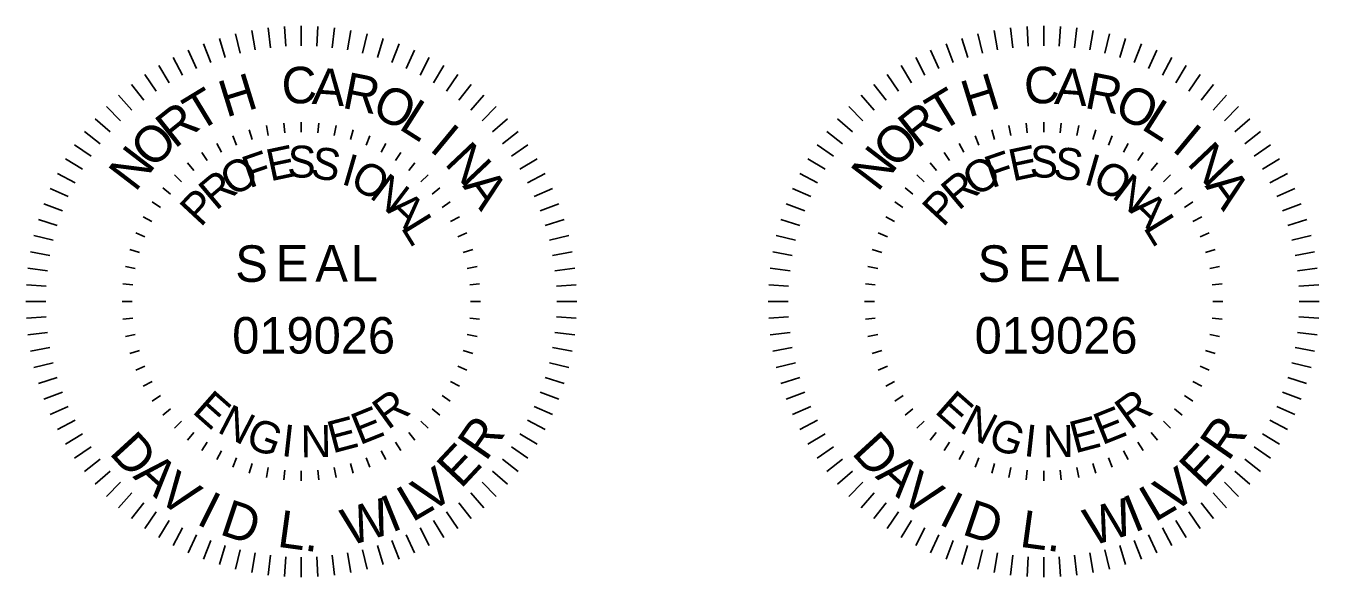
# Model space of a CAD drawing. Extents: x 1882804 to 1884487, y 844572 to 845443.
# Drawn here: x 1884080.2 to 1884256.3, y 845235.3 to 845310.3 of the extents above; entities that cross this region are included whole.
import ezdxf

# ---------------------------------------------------------------- set-up
doc = ezdxf.new("R2010")
doc.units = 0
doc.layers.add('Sheet Title CELL', color=7, linetype='Continuous')

msp = doc.modelspace()

# ---------------------------------------------------------------- linework, layer by layer
at = {"layer": 'Sheet Title CELL'}
for p, q in [((1884109.41, 845306.6), (1884108.76, 845309.24)), ((1884111.47, 845307.05), (1884110.98, 845309.71)), ((1884113.54, 845307.36), (1884113.22, 845310.05)), ((1884115.64, 845307.55), (1884115.47, 845310.26)), ((1884117.74, 845307.62), (1884117.74, 845310.33)), ((1884119.84, 845307.55), (1884120, 845310.26)), ((1884121.93, 845307.36), (1884122.26, 845310.05)), ((1884124.01, 845307.05), (1884124.5, 845309.71)), ((1884126.06, 845306.6), (1884126.71, 845309.24)), ((1884210.49, 845306.6), (1884209.84, 845309.24)), ((1884212.54, 845307.05), (1884212.05, 845309.71)), ((1884214.62, 845307.36), (1884214.29, 845310.05)), ((1884216.71, 845307.55), (1884216.55, 845310.26)), ((1884218.81, 845307.62), (1884218.81, 845310.33)), ((1884220.92, 845307.55), (1884221.08, 845310.26)), ((1884223.01, 845307.36), (1884223.34, 845310.05)), ((1884225.08, 845307.05), (1884225.57, 845309.71)), ((1884227.14, 845306.6), (1884227.79, 845309.24)), ((1884103.46, 845304.55), (1884102.35, 845307.02)), ((1884105.4, 845305.35), (1884104.44, 845307.89)), ((1884107.39, 845306.04), (1884106.58, 845308.63)), ((1884128.09, 845306.04), (1884128.89, 845308.63)), ((1884130.07, 845305.35), (1884131.04, 845307.89)), ((1884132.02, 845304.55), (1884133.13, 845307.02)), ((1884204.53, 845304.55), (1884203.42, 845307.02)), ((1884206.48, 845305.35), (1884205.52, 845307.89)), ((1884208.47, 845306.04), (1884207.66, 845308.63)), ((1884229.16, 845306.04), (1884229.97, 845308.63)), ((1884231.15, 845305.35), (1884232.11, 845307.89)), ((1884233.09, 845304.55), (1884234.2, 845307.02)), ((1884101.57, 845303.63), (1884100.31, 845306.03)), ((1884133.9, 845303.63), (1884135.16, 845306.03)), ((1884202.65, 845303.63), (1884201.39, 845306.03)), ((1884234.98, 845303.63), (1884236.24, 845306.03)), ((1884097.98, 845301.46), (1884096.43, 845303.69)), ((1884099.74, 845302.6), (1884098.34, 845304.92)), ((1884135.73, 845302.6), (1884137.14, 845304.92)), ((1884137.5, 845301.46), (1884139.04, 845303.69)), ((1884199.05, 845301.46), (1884197.51, 845303.69)), ((1884200.82, 845302.6), (1884199.41, 845304.92)), ((1884236.81, 845302.6), (1884238.21, 845304.92)), ((1884238.58, 845301.46), (1884240.12, 845303.69)), ((1884096.28, 845300.21), (1884094.61, 845302.34)), ((1884139.19, 845300.21), (1884140.86, 845302.34)), ((1884197.36, 845300.21), (1884195.69, 845302.34)), ((1884240.27, 845300.21), (1884241.94, 845302.34)), ((1884094.67, 845298.87), (1884092.87, 845300.9)), ((1884140.81, 845298.87), (1884142.61, 845300.9)), ((1884195.74, 845298.87), (1884193.95, 845300.9)), ((1884241.88, 845298.87), (1884243.68, 845300.9)), ((1884093.14, 845297.43), (1884091.22, 845299.34)), ((1884142.34, 845297.43), (1884144.25, 845299.34)), ((1884194.21, 845297.43), (1884192.3, 845299.34)), ((1884243.41, 845297.43), (1884245.33, 845299.34)), ((1884091.7, 845295.89), (1884089.67, 845297.69)), ((1884113.24, 845295.43), (1884112.98, 845296.76)), ((1884115.48, 845295.76), (1884115.35, 845297.11)), ((1884117.74, 845295.87), (1884117.74, 845297.22)), ((1884120, 845295.76), (1884120.13, 845297.11)), ((1884122.23, 845295.43), (1884122.5, 845296.76)), ((1884143.78, 845295.89), (1884145.81, 845297.69)), ((1884192.77, 845295.89), (1884190.75, 845297.69)), ((1884214.32, 845295.43), (1884214.05, 845296.76)), ((1884216.55, 845295.76), (1884216.42, 845297.11)), ((1884218.81, 845295.87), (1884218.81, 845297.22)), ((1884221.07, 845295.76), (1884221.2, 845297.11)), ((1884223.31, 845295.43), (1884223.58, 845296.76)), ((1884244.85, 845295.89), (1884246.88, 845297.69)), ((1884090.35, 845294.28), (1884088.22, 845295.95)), ((1884108.92, 845294.11), (1884108.4, 845295.37)), ((1884111.05, 845294.88), (1884110.65, 845296.17)), ((1884124.43, 845294.88), (1884124.82, 845296.17)), ((1884126.56, 845294.11), (1884127.07, 845295.37)), ((1884145.12, 845294.28), (1884147.26, 845295.95)), ((1884191.43, 845294.28), (1884189.29, 845295.95)), ((1884210, 845294.11), (1884209.48, 845295.37)), ((1884212.13, 845294.88), (1884211.73, 845296.17)), ((1884225.5, 845294.88), (1884225.9, 845296.17)), ((1884227.63, 845294.11), (1884228.15, 845295.37)), ((1884246.2, 845294.28), (1884248.34, 845295.95)), ((1884089.11, 845292.59), (1884086.88, 845294.13)), ((1884104.94, 845291.99), (1884104.18, 845293.11)), ((1884106.88, 845293.15), (1884106.24, 845294.34)), ((1884128.6, 845293.15), (1884129.24, 845294.34)), ((1884130.54, 845291.99), (1884131.29, 845293.11)), ((1884146.37, 845292.59), (1884148.6, 845294.13)), ((1884190.18, 845292.59), (1884187.95, 845294.13)), ((1884206.01, 845291.99), (1884205.26, 845293.11)), ((1884207.95, 845293.15), (1884207.31, 845294.34)), ((1884229.68, 845293.15), (1884230.31, 845294.34)), ((1884231.62, 845291.99), (1884232.37, 845293.11)), ((1884247.45, 845292.59), (1884249.68, 845294.13)), ((1884087.97, 845290.82), (1884085.64, 845292.23)), ((1884103.12, 845290.64), (1884102.26, 845291.68)), ((1884132.36, 845290.64), (1884133.21, 845291.68)), ((1884147.51, 845290.82), (1884149.83, 845292.23)), ((1884189.04, 845290.82), (1884186.72, 845292.23)), ((1884204.2, 845290.64), (1884203.34, 845291.68)), ((1884233.43, 845290.64), (1884234.29, 845291.68)), ((1884248.59, 845290.82), (1884250.91, 845292.23)), ((1884086.93, 845288.99), (1884084.53, 845290.25)), ((1884101.44, 845289.12), (1884100.49, 845290.08)), ((1884134.03, 845289.12), (1884134.99, 845290.08)), ((1884148.54, 845288.99), (1884150.94, 845290.25)), ((1884188.01, 845288.99), (1884185.61, 845290.25)), ((1884202.52, 845289.12), (1884201.56, 845290.08)), ((1884235.11, 845289.12), (1884236.07, 845290.08)), ((1884249.62, 845288.99), (1884252.02, 845290.25)), ((1884086.01, 845287.1), (1884083.54, 845288.22)), ((1884099.93, 845287.44), (1884098.88, 845288.3)), ((1884135.55, 845287.44), (1884136.6, 845288.3)), ((1884149.46, 845287.1), (1884151.93, 845288.22)), ((1884187.09, 845287.1), (1884184.62, 845288.22)), ((1884201, 845287.44), (1884199.95, 845288.3)), ((1884236.63, 845287.44), (1884237.67, 845288.3)), ((1884250.54, 845287.1), (1884253.01, 845288.22)), ((1884085.21, 845285.16), (1884082.67, 845286.12)), ((1884098.58, 845285.63), (1884097.45, 845286.38)), ((1884136.9, 845285.63), (1884138.02, 845286.38)), ((1884150.27, 845285.16), (1884152.8, 845286.12)), ((1884186.29, 845285.16), (1884183.75, 845286.12)), ((1884199.65, 845285.63), (1884198.53, 845286.38)), ((1884237.97, 845285.63), (1884239.1, 845286.38)), ((1884251.34, 845285.16), (1884253.88, 845286.12)), ((1884097.41, 845283.69), (1884096.22, 845284.33)), ((1884138.06, 845283.69), (1884139.26, 845284.33)), ((1884198.49, 845283.69), (1884197.3, 845284.33)), ((1884239.14, 845283.69), (1884240.33, 845284.33)), ((1884084.52, 845283.18), (1884081.94, 845283.98)), ((1884150.95, 845283.18), (1884153.54, 845283.98)), ((1884185.6, 845283.18), (1884183.01, 845283.98)), ((1884252.03, 845283.18), (1884254.62, 845283.98)), ((1884083.96, 845281.15), (1884081.33, 845281.8)), ((1884096.45, 845281.64), (1884095.2, 845282.16)), ((1884139.03, 845281.64), (1884140.28, 845282.16)), ((1884151.52, 845281.15), (1884154.15, 845281.8)), ((1884185.04, 845281.15), (1884182.4, 845281.8)), ((1884197.53, 845281.64), (1884196.27, 845282.16)), ((1884240.1, 845281.64), (1884241.36, 845282.16)), ((1884252.59, 845281.15), (1884255.23, 845281.8)), ((1884083.52, 845279.1), (1884080.85, 845279.58)), ((1884095.69, 845279.51), (1884094.39, 845279.91)), ((1884139.79, 845279.51), (1884141.09, 845279.91)), ((1884151.96, 845279.1), (1884154.62, 845279.58)), ((1884184.59, 845279.1), (1884181.93, 845279.58)), ((1884196.76, 845279.51), (1884195.47, 845279.91)), ((1884240.86, 845279.51), (1884242.16, 845279.91)), ((1884253.03, 845279.1), (1884255.7, 845279.58)), ((1884083.2, 845277.02), (1884080.51, 845277.35)), ((1884095.14, 845277.32), (1884093.81, 845277.58)), ((1884140.34, 845277.32), (1884141.67, 845277.58)), ((1884152.27, 845277.02), (1884154.96, 845277.35)), ((1884184.28, 845277.02), (1884181.59, 845277.35)), ((1884196.21, 845277.32), (1884194.89, 845277.58)), ((1884241.41, 845277.32), (1884242.74, 845277.58)), ((1884253.35, 845277.02), (1884256.04, 845277.35)), ((1884083.01, 845274.92), (1884080.31, 845275.09)), ((1884094.81, 845275.08), (1884093.46, 845275.22)), ((1884140.67, 845275.08), (1884142.02, 845275.22)), ((1884152.46, 845274.92), (1884155.17, 845275.09)), ((1884184.09, 845274.92), (1884181.38, 845275.09)), ((1884195.88, 845275.08), (1884194.53, 845275.22)), ((1884241.75, 845275.08), (1884243.09, 845275.22)), ((1884253.54, 845274.92), (1884256.25, 845275.09)), ((1884082.95, 845272.83), (1884080.24, 845272.83)), ((1884094.69, 845272.83), (1884093.34, 845272.83)), ((1884140.78, 845272.83), (1884142.13, 845272.83)), ((1884152.53, 845272.83), (1884155.24, 845272.83)), ((1884184.02, 845272.83), (1884181.31, 845272.83)), ((1884195.77, 845272.83), (1884194.42, 845272.83)), ((1884241.86, 845272.83), (1884243.21, 845272.83)), ((1884253.6, 845272.83), (1884256.31, 845272.83)), ((1884083.01, 845270.72), (1884080.31, 845270.56)), ((1884094.81, 845270.57), (1884093.46, 845270.44)), ((1884140.67, 845270.57), (1884142.02, 845270.44)), ((1884152.46, 845270.72), (1884155.17, 845270.56)), ((1884184.09, 845270.72), (1884181.38, 845270.56)), ((1884195.88, 845270.57), (1884194.53, 845270.44)), ((1884241.75, 845270.57), (1884243.09, 845270.44)), ((1884253.54, 845270.72), (1884256.25, 845270.56)), ((1884083.2, 845268.63), (1884080.51, 845268.31)), ((1884095.14, 845268.33), (1884093.81, 845268.07)), ((1884140.34, 845268.33), (1884141.67, 845268.07)), ((1884152.27, 845268.63), (1884154.96, 845268.31)), ((1884184.28, 845268.63), (1884181.59, 845268.31)), ((1884196.21, 845268.33), (1884194.88, 845268.07)), ((1884241.41, 845268.33), (1884242.74, 845268.07)), ((1884253.35, 845268.63), (1884256.04, 845268.31)), ((1884083.52, 845266.55), (1884080.85, 845266.07)), ((1884151.96, 845266.55), (1884154.62, 845266.07)), ((1884184.59, 845266.55), (1884181.93, 845266.07)), ((1884253.03, 845266.55), (1884255.7, 845266.07)), ((1884095.69, 845266.14), (1884094.39, 845265.74)), ((1884139.79, 845266.14), (1884141.09, 845265.74)), ((1884196.77, 845266.14), (1884195.47, 845265.74)), ((1884240.86, 845266.14), (1884242.16, 845265.74)), ((1884083.96, 845264.5), (1884081.33, 845263.85)), ((1884096.45, 845264.01), (1884095.2, 845263.49)), ((1884139.03, 845264.01), (1884140.28, 845263.49)), ((1884151.52, 845264.5), (1884154.15, 845263.85)), ((1884185.04, 845264.5), (1884182.4, 845263.85)), ((1884197.53, 845264.01), (1884196.27, 845263.49)), ((1884240.1, 845264.01), (1884241.36, 845263.49)), ((1884252.59, 845264.5), (1884255.23, 845263.85)), ((1884084.52, 845262.48), (1884081.94, 845261.67)), ((1884097.42, 845261.96), (1884096.22, 845261.32)), ((1884138.06, 845261.96), (1884139.26, 845261.32)), ((1884150.95, 845262.47), (1884153.54, 845261.67)), ((1884185.6, 845262.48), (1884183.01, 845261.67)), ((1884198.49, 845261.96), (1884197.3, 845261.32)), ((1884239.14, 845261.96), (1884240.33, 845261.32)), ((1884252.03, 845262.47), (1884254.61, 845261.67)), ((1884085.21, 845260.49), (1884082.67, 845259.53)), ((1884098.58, 845260.02), (1884097.45, 845259.27)), ((1884136.9, 845260.02), (1884138.02, 845259.27)), ((1884150.27, 845260.49), (1884152.8, 845259.53)), ((1884186.29, 845260.49), (1884183.75, 845259.53)), ((1884199.66, 845260.02), (1884198.53, 845259.27)), ((1884237.97, 845260.02), (1884239.1, 845259.27)), ((1884251.34, 845260.49), (1884253.88, 845259.53)), ((1884086.01, 845258.55), (1884083.54, 845257.43)), ((1884099.93, 845258.21), (1884098.88, 845257.35)), ((1884135.55, 845258.21), (1884136.6, 845257.35)), ((1884149.46, 845258.55), (1884151.93, 845257.43)), ((1884187.09, 845258.55), (1884184.62, 845257.43)), ((1884201, 845258.21), (1884199.95, 845257.35)), ((1884236.63, 845258.21), (1884237.67, 845257.35)), ((1884250.54, 845258.55), (1884253.01, 845257.43)), ((1884086.93, 845256.66), (1884084.53, 845255.4)), ((1884101.44, 845256.53), (1884100.49, 845255.57)), ((1884134.03, 845256.53), (1884134.99, 845255.57)), ((1884148.54, 845256.66), (1884150.94, 845255.4)), ((1884188.01, 845256.66), (1884185.61, 845255.4)), ((1884202.52, 845256.53), (1884201.56, 845255.57)), ((1884235.11, 845256.53), (1884236.07, 845255.57)), ((1884249.62, 845256.66), (1884252.02, 845255.4)), ((1884087.97, 845254.83), (1884085.64, 845253.42)), ((1884103.12, 845255.01), (1884102.26, 845253.97)), ((1884132.36, 845255.01), (1884133.21, 845253.97)), ((1884147.51, 845254.83), (1884149.83, 845253.42)), ((1884189.04, 845254.83), (1884186.72, 845253.42)), ((1884204.19, 845255.01), (1884203.34, 845253.97)), ((1884233.43, 845255.01), (1884234.29, 845253.97)), ((1884248.59, 845254.83), (1884250.91, 845253.42)), ((1884089.11, 845253.06), (1884086.88, 845251.52)), ((1884104.94, 845253.67), (1884104.18, 845252.54)), ((1884106.88, 845252.5), (1884106.24, 845251.31)), ((1884128.6, 845252.5), (1884129.24, 845251.31)), ((1884130.54, 845253.67), (1884131.29, 845252.54)), ((1884146.37, 845253.06), (1884148.6, 845251.52)), ((1884190.18, 845253.06), (1884187.95, 845251.52)), ((1884206.01, 845253.67), (1884205.26, 845252.54)), ((1884207.95, 845252.5), (1884207.31, 845251.31)), ((1884229.68, 845252.5), (1884230.31, 845251.31)), ((1884231.61, 845253.67), (1884232.37, 845252.54)), ((1884247.45, 845253.06), (1884249.68, 845251.52)), ((1884090.35, 845251.37), (1884088.22, 845249.7)), ((1884108.92, 845251.54), (1884108.4, 845250.29)), ((1884111.05, 845250.77), (1884110.65, 845249.48)), ((1884124.43, 845250.77), (1884124.82, 845249.48)), ((1884126.56, 845251.54), (1884127.07, 845250.29)), ((1884145.12, 845251.37), (1884147.26, 845249.7)), ((1884191.43, 845251.37), (1884189.29, 845249.7)), ((1884210, 845251.54), (1884209.48, 845250.29)), ((1884212.13, 845250.77), (1884211.73, 845249.48)), ((1884225.5, 845250.77), (1884225.9, 845249.48)), ((1884227.63, 845251.54), (1884228.15, 845250.29)), ((1884246.2, 845251.37), (1884248.34, 845249.7)), ((1884091.7, 845249.76), (1884089.67, 845247.96)), ((1884113.24, 845250.23), (1884112.98, 845248.9)), ((1884115.48, 845249.89), (1884115.35, 845248.55)), ((1884117.74, 845249.78), (1884117.74, 845248.43)), ((1884120, 845249.89), (1884120.13, 845248.55)), ((1884122.23, 845250.23), (1884122.5, 845248.9)), ((1884143.78, 845249.76), (1884145.81, 845247.96)), ((1884192.77, 845249.76), (1884190.75, 845247.96)), ((1884214.32, 845250.23), (1884214.05, 845248.9)), ((1884216.55, 845249.89), (1884216.42, 845248.55)), ((1884218.81, 845249.78), (1884218.81, 845248.43)), ((1884221.07, 845249.89), (1884221.2, 845248.55)), ((1884223.31, 845250.23), (1884223.58, 845248.9)), ((1884244.85, 845249.76), (1884246.88, 845247.96)), ((1884093.14, 845248.23), (1884091.22, 845246.31)), ((1884142.34, 845248.23), (1884144.25, 845246.31)), ((1884194.21, 845248.23), (1884192.3, 845246.31)), ((1884243.41, 845248.23), (1884245.33, 845246.31)), ((1884094.67, 845246.79), (1884092.87, 845244.76)), ((1884096.28, 845245.44), (1884094.61, 845243.31)), ((1884139.19, 845245.44), (1884140.87, 845243.31)), ((1884140.81, 845246.79), (1884142.61, 845244.76)), ((1884195.74, 845246.79), (1884193.95, 845244.76)), ((1884197.36, 845245.44), (1884195.69, 845243.31)), ((1884240.27, 845245.44), (1884241.94, 845243.31)), ((1884241.88, 845246.79), (1884243.68, 845244.76)), ((1884097.98, 845244.19), (1884096.43, 845241.96)), ((1884137.5, 845244.19), (1884139.04, 845241.96)), ((1884199.05, 845244.19), (1884197.51, 845241.96)), ((1884238.58, 845244.19), (1884240.12, 845241.96)), ((1884099.74, 845243.05), (1884098.34, 845240.73)), ((1884101.57, 845242.02), (1884100.31, 845239.62)), ((1884133.9, 845242.02), (1884135.16, 845239.62)), ((1884135.73, 845243.05), (1884137.14, 845240.73)), ((1884200.82, 845243.05), (1884199.41, 845240.73)), ((1884202.65, 845242.02), (1884201.39, 845239.62)), ((1884234.98, 845242.02), (1884236.24, 845239.62)), ((1884236.81, 845243.05), (1884238.21, 845240.73)), ((1884103.46, 845241.1), (1884102.35, 845238.63)), ((1884105.4, 845240.3), (1884104.44, 845237.76)), ((1884130.07, 845240.3), (1884131.04, 845237.76)), ((1884132.02, 845241.1), (1884133.13, 845238.63)), ((1884204.53, 845241.1), (1884203.42, 845238.63)), ((1884206.48, 845240.3), (1884205.52, 845237.76)), ((1884231.15, 845240.3), (1884232.11, 845237.76)), ((1884233.09, 845241.1), (1884234.2, 845238.63)), ((1884107.39, 845239.61), (1884106.58, 845237.02)), ((1884109.41, 845239.05), (1884108.76, 845236.42)), ((1884111.47, 845238.61), (1884110.98, 845235.94)), ((1884124.01, 845238.61), (1884124.5, 845235.94)), ((1884126.06, 845239.05), (1884126.71, 845236.42)), ((1884128.09, 845239.61), (1884128.89, 845237.02)), ((1884208.46, 845239.61), (1884207.66, 845237.02)), ((1884210.49, 845239.05), (1884209.84, 845236.42)), ((1884212.54, 845238.61), (1884212.05, 845235.94)), ((1884225.09, 845238.61), (1884225.57, 845235.94)), ((1884227.14, 845239.05), (1884227.79, 845236.42)), ((1884229.16, 845239.61), (1884229.97, 845237.02)), ((1884113.54, 845238.29), (1884113.22, 845235.6)), ((1884115.64, 845238.1), (1884115.47, 845235.39)), ((1884117.74, 845238.04), (1884117.74, 845235.33)), ((1884119.84, 845238.1), (1884120, 845235.39)), ((1884121.93, 845238.29), (1884122.26, 845235.6)), ((1884214.62, 845238.29), (1884214.29, 845235.6)), ((1884216.71, 845238.1), (1884216.55, 845235.39)), ((1884218.81, 845238.04), (1884218.81, 845235.33)), ((1884220.92, 845238.1), (1884221.08, 845235.39)), ((1884223.01, 845238.29), (1884223.33, 845235.6))]:
    msp.add_line(p, q, dxfattribs=at)

# ---------------------------------------------------------------- texts
for s, height, rotation, p in [('H', 4.97, 17.1424, (1884107.49, 845297.84)), ('C', 4.97, 2.9639, (1884115.18, 845299.66)), ('A', 4.97, 355.8747, (1884119.12, 845299.72)), ('R', 4.97, 348.7854, (1884123.15, 845299.2)), ('H', 4.97, 17.1424, (1884208.57, 845297.84)), ('C', 4.97, 2.9639, (1884216.26, 845299.66)), ('A', 4.97, 355.8747, (1884220.2, 845299.72)), ('R', 4.97, 348.7854, (1884224.23, 845299.2)), ('T', 4.97, 31.3208, (1884103.71, 845295.81)), ('O', 4.97, 334.607, (1884127.1, 845298.19)), ('T', 4.97, 31.3208, (1884204.79, 845295.81)), ('O', 4.97, 334.607, (1884228.17, 845298.19)), ('L', 4.97, 327.5178, (1884130.85, 845296.4)), ('L', 4.97, 327.5178, (1884231.93, 845296.4)), ('R', 4.97, 38.4101, (1884100.5, 845293.53)), ('R', 4.97, 38.4101, (1884201.58, 845293.53)), ('O', 4.97, 45.4993, (1884097.56, 845290.72)), ('I', 4.97, 320.4285, (1884135.03, 845293.47)), ('O', 4.97, 45.4993, (1884198.64, 845290.72)), ('I', 4.97, 320.4285, (1884236.11, 845293.47)), ('N', 4.97, 52.5885, (1884095.14, 845287.6)), ('F', 4.34, 18.9978, (1884110.65, 845288.21)), ('E', 4.34, 11.9657, (1884113.51, 845289.16)), ('S', 4.34, 357.9015, (1884115.78, 845289.76)), ('S', 4.34, 350.8693, (1884118.87, 845289.71)), ('N', 4.97, 313.3393, (1884137.09, 845291.55)), ('N', 4.97, 52.5885, (1884196.22, 845287.6)), ('F', 4.34, 18.9978, (1884211.73, 845288.21)), ('E', 4.34, 11.9657, (1884214.58, 845289.16)), ('S', 4.34, 357.9015, (1884216.85, 845289.76)), ('S', 4.34, 350.8693, (1884219.94, 845289.71)), ('N', 4.97, 313.3393, (1884238.17, 845291.55)), ('O', 4.34, 33.0621, (1884108.52, 845286.94)), ('I', 4.34, 343.8372, (1884123.03, 845288.84)), ('O', 4.34, 329.773, (1884124.13, 845288.61)), ('O', 4.34, 33.0621, (1884209.59, 845286.94)), ('I', 4.34, 343.8372, (1884224.11, 845288.84)), ('O', 4.34, 329.773, (1884225.2, 845288.61)), ('R', 4.34, 40.0942, (1884106.13, 845285.09)), ('N', 4.34, 322.7408, (1884126.87, 845287.05)), ('A', 4.97, 306.2501, (1884139.62, 845288.53)), ('R', 4.34, 40.0942, (1884207.21, 845285.09)), ('N', 4.34, 322.7408, (1884227.94, 845287.05)), ('A', 4.97, 306.2501, (1884240.69, 845288.53)), ('P', 4.34, 47.1263, (1884104.03, 845282.83)), ('P', 4.34, 47.1263, (1884205.1, 845282.83)), ('A', 4.34, 315.7087, (1884129.22, 845285.17)), ('A', 4.34, 315.7087, (1884230.3, 845285.17)), ('L', 4.34, 301.6445, (1884131.21, 845282.9)), ('L', 4.34, 301.6445, (1884232.29, 845282.9)), ('S', 4.97, 359.9999, (1884108.75, 845275.5)), ('E', 4.97, 359.9999, (1884114.26, 845275.55)), ('A', 4.97, 359.9999, (1884119.65, 845275.53)), ('L', 4.97, 359.9999, (1884124.46, 845275.55)), ('S', 4.97, 359.9999, (1884209.82, 845275.5)), ('E', 4.97, 359.9999, (1884215.33, 845275.55)), ('A', 4.97, 359.9999, (1884220.72, 845275.53)), ('L', 4.97, 359.9999, (1884225.53, 845275.55)), ('019026', 4.97, 359.9999, (1884108.33, 845265.74)), ('019026', 4.97, 359.9999, (1884209.41, 845265.74)), ('E', 4.34, 318.5439, (1884102.74, 845257.77)), ('R', 4.34, 35.8972, (1884129.51, 845255.27)), ('E', 4.34, 318.5439, (1884203.82, 845257.77)), ('R', 4.34, 35.8972, (1884230.59, 845255.27)), ('N', 4.34, 332.6081, (1884106.14, 845255.13)), ('E', 4.34, 21.8329, (1884125.69, 845253.25)), ('N', 4.34, 332.6081, (1884207.22, 845255.13)), ('E', 4.34, 21.8329, (1884226.76, 845253.25)), ('G', 4.34, 339.6402, (1884109.94, 845253.12)), ('I', 4.34, 353.7045, (1884114.92, 845251.82)), ('N', 4.34, 0.7366, (1884117.66, 845251.63)), ('E', 4.34, 14.8008, (1884121.98, 845252.14)), ('R', 5.05, 55.2833, (1884142.87, 845250.94)), ('G', 4.34, 339.6402, (1884211.01, 845253.12)), ('I', 4.34, 353.7045, (1884215.99, 845251.82)), ('N', 4.34, 0.7366, (1884218.74, 845251.63)), ('E', 4.34, 14.8008, (1884223.05, 845252.14)), ('R', 5.05, 55.2833, (1884243.94, 845250.94)), ('D', 5.05, 312.4628, (1884091.46, 845252.16)), ('D', 5.05, 312.4628, (1884192.54, 845252.16)), ('E', 5.05, 46.8907, (1884139.46, 845247.23)), ('E', 5.05, 46.8907, (1884240.54, 845247.23)), ('A', 5.05, 317.9071, (1884094.7, 845248.94)), ('A', 5.05, 317.9071, (1884195.78, 845248.94)), ('V', 5.05, 323.9535, (1884097.88, 845245.99)), ('V', 5.05, 35.27, (1884135.2, 845243.88)), ('V', 5.05, 323.9535, (1884198.96, 845245.99)), ('V', 5.05, 35.27, (1884236.27, 845243.88)), ('L', 5.05, 30.5805, (1884132.84, 845242.73)), ('L', 5.05, 30.5805, (1884233.91, 845242.73)), ('I', 5.05, 333.3754, (1884103.28, 845242.63)), ('D', 5.05, 341.5338, (1884106.46, 845241.19)), ('W', 5.05, 16.5242, (1884124.17, 845239.52)), ('I', 5.05, 22.0503, (1884130.02, 845241.33)), ('I', 5.05, 333.3754, (1884204.36, 845242.63)), ('D', 5.05, 341.5338, (1884207.53, 845241.19)), ('W', 5.05, 16.5242, (1884225.25, 845239.52)), ('I', 5.05, 22.0503, (1884231.1, 845241.33)), ('L.', 5.048, 352.1953, (1884114.35, 845239.48)), ('L.', 5.048, 352.1953, (1884215.42, 845239.48))]:
    msp.add_text(s, height=height, rotation=rotation, dxfattribs=at).set_placement(p)

doc.saveas('drawing.dxf')
